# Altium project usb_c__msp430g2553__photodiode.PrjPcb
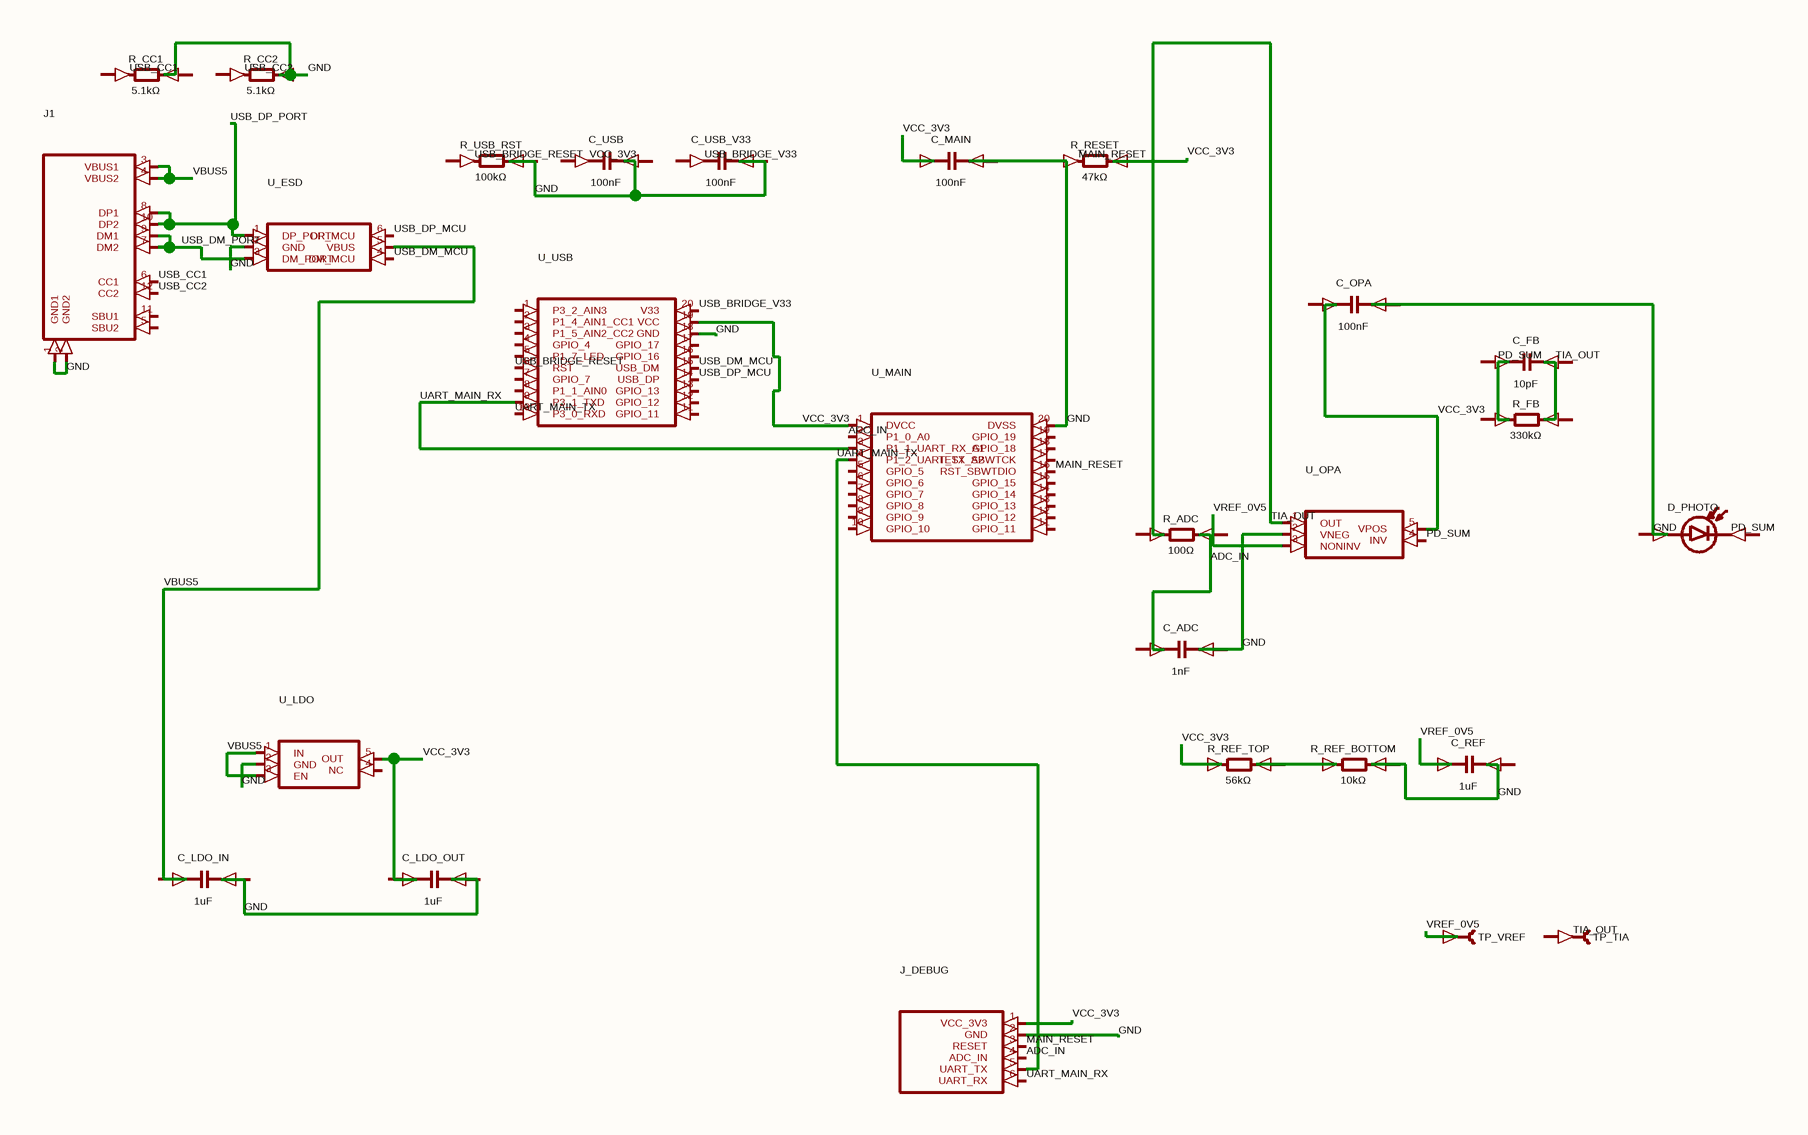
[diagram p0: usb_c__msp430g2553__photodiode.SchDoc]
1 sheet, 27 parts. Net scope: global (net labels, ports and power ports of the same name join across sheets).
Board file: usb_c__msp430g2553__photodiode.PcbDoc

## Sheet usb_c__msp430g2553__photodiode.SchDoc
size 200 x 142 mm

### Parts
C_ADC  1nF
C_FB  10pF
C_LDO_IN  1uF
C_LDO_OUT  1uF
C_MAIN  100nF
C_OPA  100nF
C_REF  1uF
C_USB  100nF
C_USB_V33  100nF
D_PHOTO  (no value)
J1  (no value)
J_DEBUG  (no value)
R_ADC  100Ω
R_CC1  5.1kΩ
R_CC2  5.1kΩ
R_FB  330kΩ
R_REF_BOTTOM  10kΩ
R_REF_TOP  56kΩ
R_RESET  47kΩ
R_USB_RST  100kΩ
TP_TIA  (no value)
TP_VREF  (no value)
U_ESD  (no value)
U_LDO  (no value)
U_MAIN  (no value)
U_OPA  (no value)
U_USB  (no value)

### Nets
ADC_IN: J_DEBUG.4(ADC_IN) U_MAIN.2(P1_0_A0)
GND: C_ADC.2(neg) C_MAIN.2(neg) C_OPA.2(neg) C_REF.1(pos) J1.1(GND1) J1.2(GND2) J_DEBUG.2(GND) R_CC2.2(cathode) R_REF_BOTTOM.2(cathode) R_RESET.1(anode) TP_VREF.1(pin1) U_ESD.2(GND) U_LDO.2(GND) U_MAIN.20(DVSS) U_OPA.2(VNEG) U_OPA.3(NONINV) U_USB.18(GND)  [also labelled VREF_0V5]
MAIN_RESET: J_DEBUG.3(RESET) U_MAIN.16(RST_SBWTDIO)
PD_SUM: U_OPA.4(INV)
TIA_OUT: U_OPA.1(OUT)
UART_MAIN_RX: J_DEBUG.6(UART_RX) U_MAIN.3(P1_1_UART_RX_A1) U_USB.9(P3_1_TXD)
UART_MAIN_TX: J_DEBUG.5(UART_TX) U_MAIN.4(P1_2_UART_TX_A2) U_USB.10(P3_0_RXD)
USB_BRIDGE_RESET: U_USB.6(RST)
USB_BRIDGE_V33: U_USB.20(V33)
USB_CC1: J1.6(CC1)
USB_CC2: J1.12(CC2)
USB_DM_MCU: U_ESD.4(DM_MCU) U_USB.15(USB_DM)
USB_DM_PORT: J1.7(DM2) J1.9(DM1) U_ESD.3(DM_PORT)
USB_DP_MCU: U_ESD.6(DP_MCU) U_USB.14(USB_DP)
USB_DP_PORT: J1.8(DP1) J1.10(DP2) U_ESD.1(DP_PORT)
VBUS5: J1.3(VBUS1) J1.4(VBUS2) U_ESD.5(VBUS) U_LDO.1(IN) U_LDO.3(EN)
VCC_3V3: C_MAIN.1(pos) J_DEBUG.1(VCC_3V3) R_REF_TOP.1(anode) R_RESET.2(cathode) U_LDO.5(OUT) U_MAIN.1(DVCC) U_OPA.5(VPOS) U_USB.19(VCC)
NetR_REF_BOTTOM_1: R_REF_BOTTOM.1(anode) R_REF_TOP.2(cathode)

Not connected (* = marked no-connect by the designer): C_ADC 1(pos); C_FB 1(pos) 2(neg); C_LDO_IN 1(pos) 2(neg); C_LDO_OUT 1(pos) 2(neg); C_OPA 1(pos); C_REF 2(neg); C_USB 1(pos) 2(neg); C_USB_V33 1(pos) 2(neg); D_PHOTO 1(anode) 2(cathode); J1 5(SBU2) 11(SBU1); R_ADC 1(anode) 2(cathode); R_CC1 1(anode) 2(cathode); R_CC2 1(anode); R_FB 1(anode) 2(cathode); R_USB_RST 1(anode) 2(cathode); TP_TIA 1(pin1); U_LDO 4(NC); U_MAIN 5(GPIO_5) 6(GPIO_6) 7(GPIO_7) 8(GPIO_8) 9(GPIO_9) 10(GPIO_10) 11(GPIO_11) 12(GPIO_12) 13(GPIO_13) 14(GPIO_14) 15(GPIO_15) 17(TEST_SBWTCK) 18(GPIO_18) 19(GPIO_19); U_USB 1(P3_2_AIN3) 2(P1_4_AIN1_CC1) 3(P1_5_AIN2_CC2) 4(GPIO_4) 5(P1_7_LED) 7(GPIO_7) 8(P1_1_AIN0) 11(GPIO_11) 12(GPIO_12) 13(GPIO_13) 16(GPIO_16) 17(GPIO_17)

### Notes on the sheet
- Labels drawn without touching a wire or pin: MAIN_RESET, PD_SUM, TIA_OUT, USB_BRIDGE_RESET, USB_BRIDGE_V33, USB_CC1, USB_CC2, VCC_3V3

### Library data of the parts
C_ADC C_FB C_LDO_IN C_LDO_OUT C_MAIN C_OPA C_REF C_USB C_USB_V33 = capacitor_right
D_PHOTO = photodiode_horz
J1 = J1
J_DEBUG = J_DEBUG
R_ADC R_CC1 R_CC2 R_FB R_REF_BOTTOM R_REF_TOP R_RESET R_USB_RST = boxresistor_right
TP_TIA TP_VREF = testpoint_right
U_ESD = U_ESD
U_LDO = U_LDO
U_MAIN = U_MAIN
U_OPA = U_OPA
U_USB = U_USB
